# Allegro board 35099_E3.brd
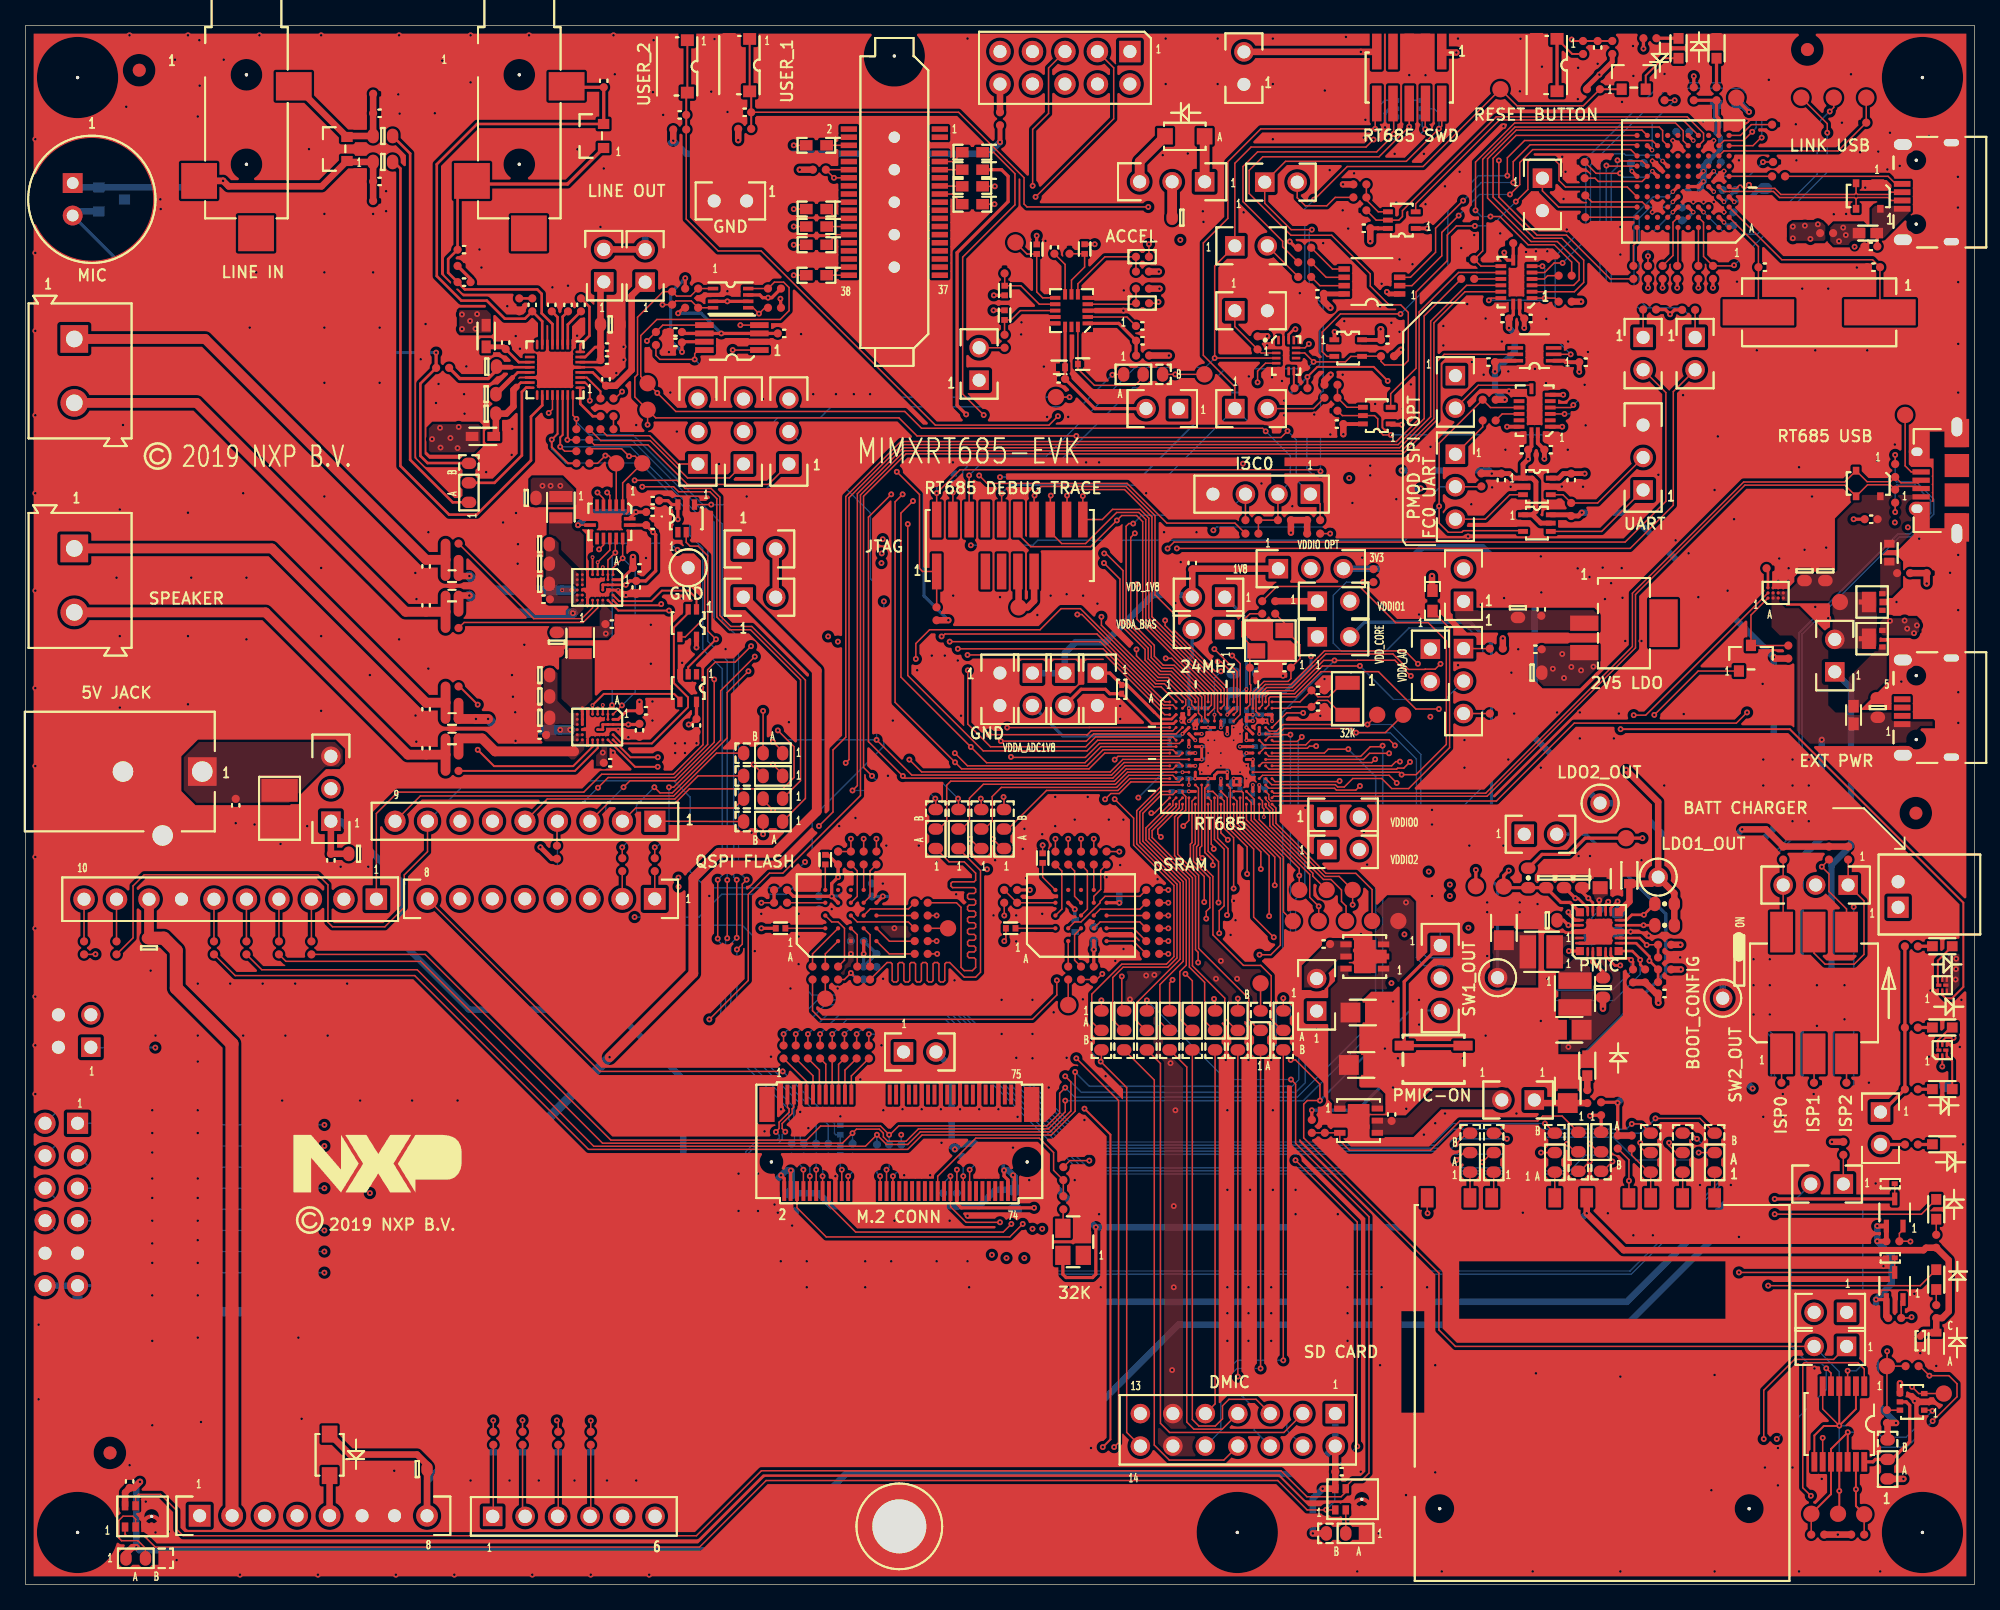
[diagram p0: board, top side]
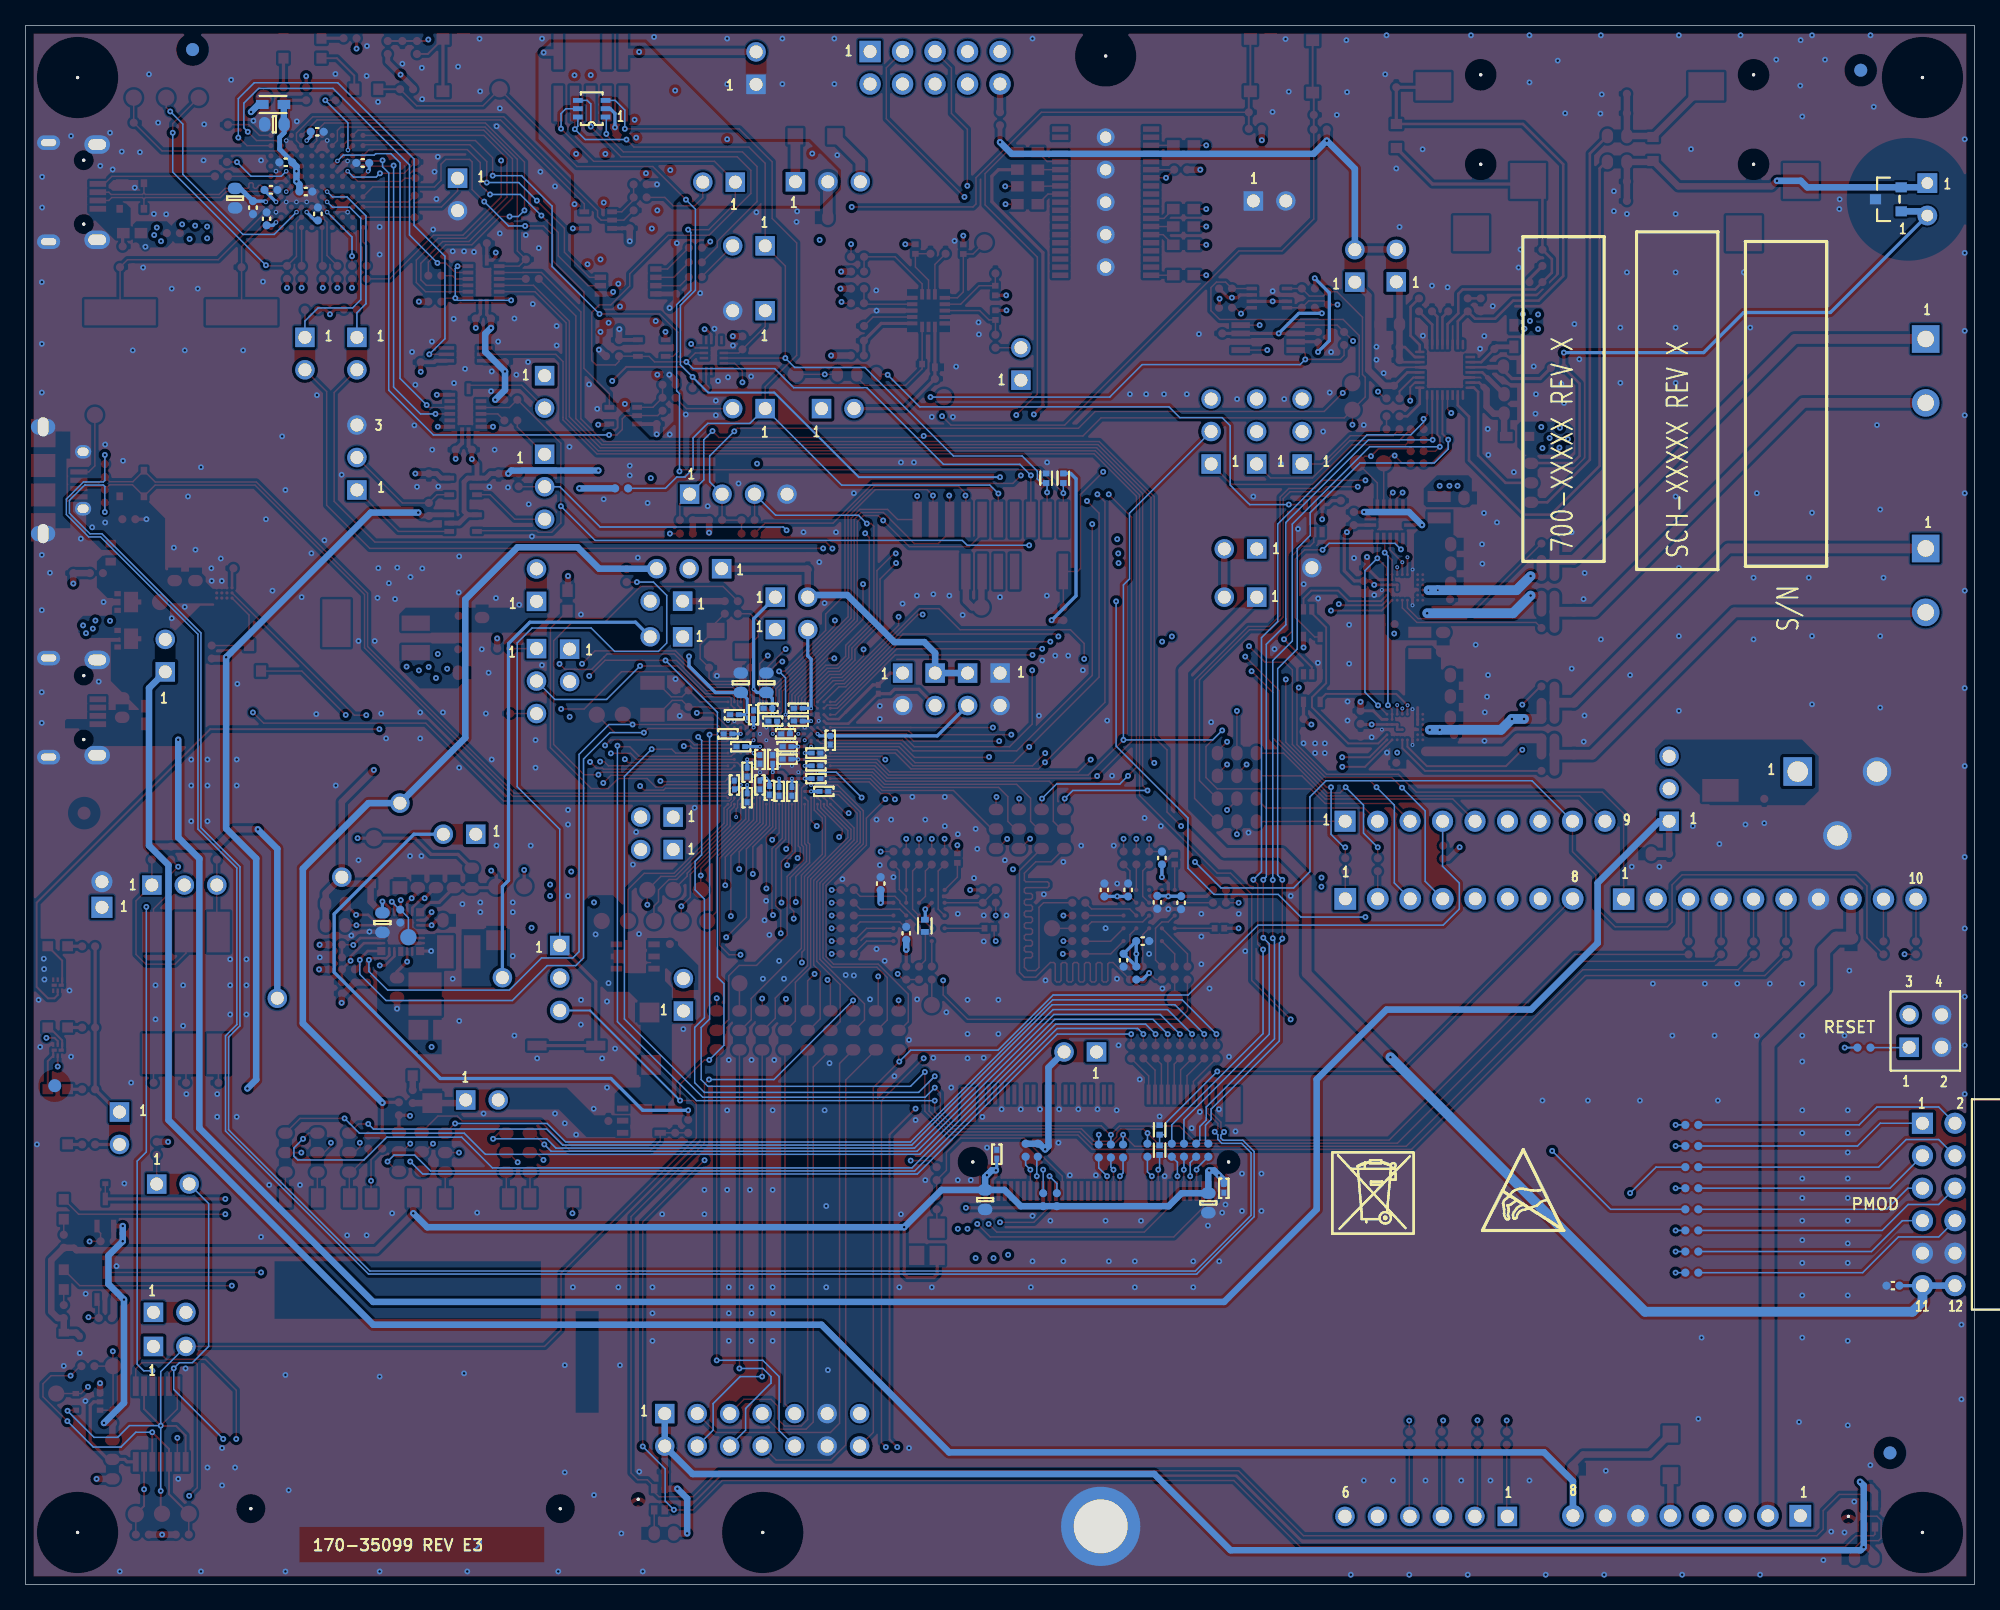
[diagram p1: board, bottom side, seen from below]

Outline 152.4 x 121.92 mm; copper layers: TOP, L2_GND, L3_IN1, L4_IN2, L5_PWR, BOTTOM. Coordinates in mm from the lower left corner of the outline.
Outline path: 0,121.92 152.4,121.92 152.4,0 0,0 0,121.92

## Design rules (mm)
constraint set DEFAULT: min track width 0.114
net group ACC_INT1: nets ACC_INT1 N18526318
net group BOOT0_LED: nets BOOT0_LED N17344064
net group BRIDGE_L_INTR-ISP: nets BRIDGE_L_INTR-ISP N17104052
net group CPCA: nets CPCA CPCB
net group FC5_RTS: nets FC5_RTS P1_7
net group HP_OUTL: nets HP_OUTL N169660511
net group HP_OUTR: nets HP_OUTR N169660621
net group IF_DETECT: nets IF_DETECT N17208284
net group IF_JTAG_TDI: nets IF_JTAG_TDI N17337803
net group IF_TCK_SWCLK: nets IF_TCK_SWCLK N19799835
net group LININL: nets LININL LININL_JACK
net group M2_USB_DN: nets M2_USB_DN USB0_DM_TRGT
net group M2_USB_DP: nets M2_USB_DP USB0_DP_TRGT
net group MCLK_CODEC: nets MCLK_CODEC P1_10_MCLK
net group N17337788: nets N17337786 N17337788
net group N19546738: nets N19546738 N19546843
net group N19830205: nets N19830205 N19830207
net group NRESET_POR: nets N16975069 NRESET_POR
net group OUTN_1: nets OUTN_1 VSN_1
net group OUTN_2: nets OUTN_2 VSN_2
net group OUTP_1: nets OUTP_1 VSP_1
net group OUTP_2: nets OUTP_2 VSP_2
net group P0_2_FC0_RX_LINK: nets N17103807 P0_2_FC0_RX_LINK
net group P0_3: nets N16974944 P0_3
net group P0_5_ADC0_0: nets N17760234 P0_5_ADC0_0
net group P0_6_ADC0_8: nets N17760260 P0_6_ADC0_8
net group P0_15_FC2_SCL: nets N16974981 P0_15_FC2_SCL
net group P0_16_FC2_SDA: nets N16975002 P0_16_FC2_SDA
net group P0_19_ADC0_2: nets N17760297 P0_19_ADC0_2
net group P0_20_ADC0_10: nets N17760315 P0_20_ADC0_10
net group P0_21: nets N19798378 P0_21
net group P0_22: nets N19798386 P0_22
net group P0_23_I2S_DATA_TX: nets N19798394 P0_23_I2S_DATA_TX
net group P0_24: nets N19798402 P0_24
net group P0_25: nets N19798410 P0_25
net group P0_29_FC4_TXD: nets N17760343 P0_29_FC4_TXD
net group P0_30_FC4_RXD: nets N17760363 P0_30_FC4_RXD
net group P1_3_SPI_CLK: nets N17760012 P1_3_SPI_CLK
net group P1_8: nets N19897088 P1_8
net group P1_20_OSPI_D0: nets P1_20_OSPI_D0 SIO0_AP
net group P1_22_OSPI_D2: nets P1_22_OSPI_D2 SIO2_AP
net group P2_26_SWDIO: nets N19799857 P2_26_SWDIO
net group QSPI_B_DQS: nets DQS_MX QSPI_B_DQS
net group SCLK_MX: nets P1_29_OSPI_B_SCK SCLK_MX
net group USB_DEBUGGER: nets USB_DM_LINK USB_DP_LINK
net group USB_ID: nets USB_ID USB_ID_LINK
net group VBAT: nets VBAT VBAT_BKUP
net group VREF_H: nets VREF_H VREF_L
net group XTALIN: nets XTALIN XTALOUT
net group ALT_INT_CODEC: nets ALT_INT_CODEC N17792155 P0_0_CODEC_ALT_IN
net group BRIDGE_INTR-ISP: nets BRIDGE_INTR-ISP N16974910 N17104054
net group BT_REG_ON_3V3: nets BT_REG_ON_3V3 N19527680 N19897050 N19897150 USDHC_SPWR WL_REG_ON_3V3
net group CARD_WR_PRT: nets CARD_WR_PRT LDO2_OUT M2_SD_CDM M2_SD_WK_B N19896842 N19896964 ON_B_SW P1_31_SD0_CMD P2_4_SD0_WR_PRT P2_9_SD0_CD SD_CMD
net group CS_AP: nets CS_AP CS_MX N16974934 N19546881 N19830189 N19830220 N19830414 NRESET_OSPI NRESET_OSPI_AP P1_13_SPI_MOSI P1_13_SPI_MOSI_A P1_19_OSPI_SSEL0 P2_19_PDM_CLK67 P2_19_PDM_CLK67_A QSPI_B_CS0 QSPI_B_DATA2 RST_AP RST_MX SIO2_MX VDD_MEM
net group DQS_AP: nets DQS_AP
net group FC1_CTS_SDA_SSEL0: nets FC1_CTS_SDA_SSEL0 P0_10 PIO0_10-FC1_CTS_SDA_SSELN0
net group FC1_SCK: nets FC1_SCK I2S_BCLK_CODEC N19897259 P0_7_I2S_CLK PIO0_7-FC1_SCK
net group FC1_TXD_SCL_MISO: nets FC1_TXD_SCL_MISO I2S_WS_CODEC N19897289 P0_8_I2S_WS PIO0_8-FC1_TXD_SCL_MISO
net group FC2_SCK: nets FC2_SCK P0_14 PIO0_14-FC2_SCK
net group FC4_CTS_SDA_SSEL0: nets FC4_CTS_SDA_SSEL0 P0_31 PIO0_31-FC4_CTS_SDA_SSELN0
net group FC5_CTS: nets FC5_CTS N17760099 P1_6_SPI_SS0
net group FC5_RXD: nets FC5_RXD N17760075 P1_5_SPI_MOSI
net group FC5_TXD: nets FC5_TXD N17760042 P1_4_SPI_MISO
net group I2S_DAO_CODEC: nets I2S_DAO_CODEC N19897327 P0_23_CODEC_DAO
net group IF_RST: nets IF_RST INT_B LDO1_OUT MODESEL0 MODESEL1 N17202709 N18503998 N19506203 N19526530 N19799787 NRESET_PB NRESET_TRGT SYSRST_B
net group LININR: nets ELECTRET_MIC LININR LININR_JACK MICBIAS N17851401
net group M2_SD_CLK: nets M2_SD_CLK N19896770 P1_30_SD0_CLK SD_CLK
net group M2_SD_DAT0: nets M2_SD_DAT0 N19896868 P2_0_SD0_D0 SD_DAT0
net group M2_SD_DAT1: nets M2_SD_DAT1 N19896897 P2_1_SD0_D1 SD_DAT1
net group M2_SD_DAT2: nets M2_SD_DAT2 N19896926 P2_2_SD0_D2 SD_DAT2
net group M2_SD_DAT3: nets M2_SD_DAT3 N19896944 P2_3_SD0_D3 SD_DAT3
net group MEM_1V8: nets MEM_1V8 N19546803 N19546823
net group NAND: nets P2_5_SD0_D4 P2_6_SD0_D5 P2_7_SD0_D6 P2_8_SD0_D7
net group P0_9_CODEC_DAI: nets I2S_DAI_CODEC N19897307 P0_9_CODEC_DAI
net group P0_17_FC2_SDA: nets N17759973 N18526137 P0_17_FC2_SDA
net group P0_18_FC2_SCL: nets N17759955 N18526135 P0_18_FC2_SCL
net group P1_21_OSPI_D1: nets SIO1_AP
net group P1_23_OSPI_D3: nets SIO3_AP
net group P1_24_OSPI_D4: nets SIO4_AP
net group P1_25_OSPI_D5: nets SIO5_AP
net group P1_26_OSPI_D6: nets SIO6_AP
net group P1_27_OSPI_D7: nets SIO7_AP
net group P2_17_PDM_CLK23_A: nets P2_17_PDM_CLK23 P2_17_PDM_CLK23_A QSPI_B_DATA4 SIO4_MX
net group P2_18_PDM_CLK45_A: nets P2_18_PDM_CLK45 P2_18_PDM_CLK45_A QSPI_B_DATA5 SIO5_MX
net group P2_21_PDM_DATA23_A: nets N20219970 P2_21_PDM_DATA23 P2_21_PDM_DATA23_A
net group P2_22_PDM_DATA45_A: nets P2_22_PDM_DATA45 P2_22_PDM_DATA45_A QSPI_B_DATA6 SIO6_MX
net group P2_23_PDM_DATA67_A: nets P2_23_PDM_DATA67 P2_23_PDM_DATA67_A QSPI_B_DATA7 SIO7_MX
net group PDM_CLK01_ONBOARD: nets P2_16_PDM_CLK01 PDM_CLK01_EXT PDM_CLK01_ONBOARD
net group PDM_DATA01_EXT: nets P2_20_PDM_DATA01 PDM_DATA01_EXT PDM_DATA01_ONBOARD
net group QSPI_B_DATA0: nets N16975000 P1_11_SPI_CLK P1_11_SPI_CLK_A QSPI_B_DATA0 SIO0_MX
net group QSPI_B_DATA1: nets N16974979 P1_12_SPI_MISO P1_12_SPI_MISO_A QSPI_B_DATA1 SIO1_MX
net group QSPI_B_DATA3: nets N16974908 P1_14_SPI_SS0 P1_14_SPI_SS0_A QSPI_B_DATA3 SIO3_MX
net group SCLK_AP: nets SCLK_AP
net group SD_RST_N: nets M2_SD_RST_B N19508206 N19531396 N19896972 P2_10_SD0_RST_N SD_RST_N VDD_TARGET
net group SEL_ON_DMIC_1: nets AVDD P1V8_CODEC SEL_ON_DMIC_1 SEL_ON_DMIC_2
net group USB1_VDD3V3: nets FC0_RXD N19519289 USB1_VDD3V3 VDD_LDO_3V3
net group V_LED: nets N17023483 N17023485 N17023487 V_LED
net group VBUS0_TARGET: nets VBUS0_TARGET
net group VDD_CODEC: nets M2_32K_3V3 MICVDD N17792148 N19898667 P2_29_I3C0_SCL P2_30_I3C0_SDA P2_31_I3C0_PUR SCL_CODEC SDA_CODEC
net group VDD_LINK: nets IF_TDO_SWO N17337994 N17338012 N17338109 N17338127 N19799813 VDD_LINK

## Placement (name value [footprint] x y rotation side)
BH1  SMTSO-M25  [MH244-166T]  68.33 4.54 0 top
C1  0.1uF  [CC0402_25]  122.94 120.21 270 top
C2  220PF  [CC0402_25]  45.21 117.6 90 top
C3  0.1uF  [CC0402_25]  56.24 115.14 180 top
C4  220PF  [CC0402_25]  27.69 115.06 0 top
C5  0.1uF  [CC0402_25]  51.16 114.94 180 top
C6  4.7uF  [CC0603_OV]  27.94 113.28 180 top
C7  4.7uF  [CC0603_OV]  27.94 111.25 180 top
C8  220PF  [CC0402_25]  27.69 109.73 0 top
C9  1uF  [CC0402_25]  144.3 104.65 180 top
C10  0.1uF  [CC0402_25]  104.65 106.07 0 top
C11  220PF  [CC0402_25]  34.29 104.39 0 top
C12  10uF  [CC0603_OV]  90.42 106.9 0 top
C13  27PF  [CC0402_25]  136.02 103.02 0 top
C14  27PF  [CC0402_25]  144.51 103.02 0 top
C15  0.1uF  [CC0402_25]  34.29 101.85 0 top
C16  0.1uF  [CC0402_25]  101.02 100.94 0 top
C17  0.1uF  [CC0402_25]  39.62 100.08 90 top
C18  2.2UF  [CC0402_25]  41.15 100.08 90 top
C19  2.2UF  [CC0402_25]  42.42 100.08 90 top
C20  2.2UF  [CC0402_25]  43.43 100.08 270 top
C21  4.7uF  [CC0603_OV]  45.72 98.55 0.3 top
C22  0.1uF  [CC0402_25]  115.49 99.01 0 top
C23  0.1uF  [CC0402_25]  117.7 99.01 0 top
C24  0.1uF  [CC0402_25]  87.35 97.27 0 top
C25  0.1uF  [CC0402_25]  106.5 97.33 180 top
C26  0.1uF  [CC0402_25]  37.54 97.13 90 top
C27  1uF  [CC0402_25]  45.47 96.77 0 top
C28  0.1uF  [CC0402_25]  80.78 94.29 180 top
C29  4.7UF  [CC0402_TOL0P2]  80.82 95.19 180 top
C30  0.1uF  [CC0402_25]  45.47 95.76 0 top
C31  0.1uF  [CC0402_25]  87.34 98.42 0 top
C32  4.7uF  [CC0603_OV]  36.07 95.25 180 top
C33  0.1uF  [CC0402_25]  45.39 94.26 90 top
C34  4.7uF  [CC0603_OV]  36.02 93.09 180 top
C35  4.7uF  [CC0603_OV]  36.02 91.57 180 top
C36  0.1uF  [CC0402_25]  102.54 90.75 0 top
C37  0.1uF  [CC0402_25]  116.99 88.75 0 top
C38  0.1uF  [CC0402_25]  119.28 88.75 0 top
C39  0.22UF  [CC0402_25]  120.87 86.37 270 top
C40  0.22UF  [CC0402_25]  115.4 86.37 270 top
C41  22uF  [CC0603_OV]  39.15 84.98 180 top
C42  2.2UF  [CC0402_25]  144.32 83.31 180 top
C43  10uF  [CC0603_OV]  40.2 81.36 180 top
C44  10uF  [CC0603_OV]  40.2 79.83 180 top
C45  18pF  [CC0402_25]  31.32 79.63 270 top
C46  1uF  [CC0402_25]  48.01 79.5 0 top
C47  4.7uF  [CC0603_OV]  139.12 79.27 90 top
C48  4.7uF  [CC0603_OV]  140.74 79.27 90 top
C49  10uF  [CC0603_OV]  40.2 78.26 180 top
C50  4.7uF  [CC0603_OV]  116.7 76.38 90 top
C51  0.1uF  [CC0402_25]  118.53 76.26 90 top
C52  1uF  [CC0402_25]  47.75 77.98 270 top
C53  0.1uF  [CC0402_25]  40.5 77.05 180 top
C54  18pF  [CC0402_25]  31.32 76.58 90 top
C55  1uF  [CC0402_25]  45.85 75.11 0 top
C56  0.1uF  [CC0402_25]  118.06 73.14 180 top
C57  22uF  [CC0603_OV]  41.55 73.69 270 top
C58  6.0PF  [CC0402_25]  96.24 71.7 0 top
C59  6.0PF  [CC0402_25]  98.44 71.7 180 top
C60  4.7uF  [CC0603_OV]  117.81 71.31 180 top
C61  10uF  [CC0603_OV]  40.22 71.12 180 top
C62  18pF  [CC0402_25]  101.07 69.93 0 top
C63  0.1uF  [CC0402_25]  52.47 67.18 270 top
C64  10uF  [CC0603_OV]  40.22 69.45 180 top
C65  18pF  [CC0402_25]  31.32 68.45 270 top
C66  1uF  [CC0402_25]  48.51 68.33 0 top
C67  4.7uF  [CC0603_OV]  144.85 68.58 90 top
C68  0.1uF  [CC0201]  85.72 70.01 90 top
C69  18pF  [CC0402_25]  101.07 68.63 0 top
C70  10uF  [CC0603_OV]  40.22 67.78 180 top
C71  1uF  [CC0402_25]  48.01 66.8 270 top
C72  0.1uF  [CC0402_25]  40.2 66.43 180 top
C73  18pF  [CC0402_25]  31.32 65.41 90 top
C74  1uF  [CC0402_25]  45.72 64.26 0 top
C75  0.1uF  [CC0402_25]  16.43 60.93 270 top
C76  100UF  [CC1210]  19.86 60.71 270 top
C77  4.7uF  [CC0603_OV]  26.04 57.14 0 top
C78  0.1uF  [CC0402_25]  23.88 56.63 270 top
C79  1.0 UF  [CC0603_OV]  120.3 55.26 90 top
C80  1.0 UF  [CC0603_OV]  118.91 55.26 90 top
C81  4.7uF  [CC0603_OV]  119 51.94 180 top
C82  2.2uF  [CC0603_0402_NSP]  123.13 55.19 90 top
C83  2.2uF  [CC0603_OV]  121.73 55.26 90 top
C84  1.0 UF  [0603_CC]  125.42 55.46 90 top
C85  10uF  [CC0603_OV]  9.65 49.78 270 top
C86  10uF  [CC0603_0805_NSP]  115.61 51.35 90 top
C87  2.2uF  [CC0603_OV]  123.35 46.68 270 top
C88  10uF  [CC0603_0805_NSP]  120.72 43.38 180 top
C89  10uF  [CC0603_0805_NSP]  120.6 38.61 90 top
C90  10uF  [CC0603_OV]  30.63 9.02 180 top
C91  4.7uF  [CC0603_OV]  132.94 114.2 0 bottom
C92  0.1uF  [CC0402_25]  129.59 113.61 180 bottom
C93  0.1uF  [CC0402_25]  132.05 111.23 0 bottom
C94  0.1uF  [CC0402_25]  126.03 111.18 0 bottom
C95  0.1uF  [CC0402_25]  133.21 109.07 180 bottom
C96  0.1uF  [CC0402_25]  130.48 108.94 180 bottom
C97  10uF  [CC0603_OV]  136.02 108.42 270 bottom
C98  0.1uF  [CC0402_25]  134.62 107.68 270 bottom
C99  0.1uF  [CC0402_25]  129.54 107.19 90 bottom
C100  0.1uF  [CC0402_25]  133.55 106.81 90 bottom
C101  10uF  [CC0603_OV]  96.47 70.52 90 bottom
C102  0.1uF  [CC0201]  96.97 68.02 0 bottom
C103  0.1uF  [CC0201]  94.34 68.52 0 bottom
C104  0.1uF  [CC0201]  90.59 64.02 180 bottom
C105  0.1uF  [CC0201]  94.97 62.52 270 bottom
C106  0.1uF  [CC0201]  97.47 66.52 0 bottom
C107  0.1uF  [CC0201]  91.97 67.52 0 bottom
C108  0.1uF  [CC0201]  95.47 68.02 90 bottom
C109  0.1uF  [CC0201]  89.47 66.02 270 bottom
C110  0.1uF  [CC0201]  92.97 66.52 0 bottom
C111  0.1uF  [CC0201]  92.85 65.52 0 bottom
C112  0.1uF  [CC0201]  93.97 67.52 0 bottom
C113  0.1uF  [CC0201]  96.47 65.52 0 bottom
C114  0.1uF  [CC0201]  90.59 65.02 180 bottom
C115  0.01uF  [CC0201]  94.97 64.52 270 bottom
C116  0.1uF  [CC0201]  92.85 64.55 0 bottom
C117  0.1uF  [CC0201]  95.97 63.52 270 bottom
C118  10uF  [CC0603_OV]  94.47 70.52 90 bottom
C119  0.1uF  [CC0201]  93.47 62.02 270 bottom
C120  0.1uF  [CC0201]  92.47 62.02 270 bottom
C121  0.1uF  [CC0201]  93.97 64.52 90 bottom
C122  0.1uF  [CC0201]  90.59 63.02 180 bottom
C123  0.1uF  [CC0201]  96.97 62.52 90 bottom
C124  0.1uF  [CC0201]  94.23 62.1 270 bottom
C125  0.1uF  [CC0201]  89.97 62.02 180 bottom
C126  0.1uF  [CC0201]  95.97 61.52 270 bottom
C127  2.2UF  [CC0402_25]  63.54 56.81 90 bottom
C128  0.1uF  [CC0402_25]  65.04 50.32 180 bottom
C129  0.1uF  [CC0402_25]  62.04 53.32 270 bottom
C130  2.2UF  [CC0402_25]  66.18 54.32 90 bottom
C131  0.47UF  [CC0603_OV]  124.5 51.76 270 bottom
C132  0.1uF  [CC0402_25]  63.9 53.35 270 bottom
C133  2.2UF  [CC0402_25]  68.04 54.32 90 bottom
C134  0.1uF  [CC0402_25]  6.37 23.37 180 bottom
C135  10uF  [CC0603_0805_NSP]  104.44 40.63 0 top
C136  0.1uF  [CC0402_25]  106.82 36.76 90 top
C137  10uF  [CC0603_0805_NSP]  104.57 44.73 0 top
C138  0.1uF  [CC0402_25]  101.51 50.09 180 top
C139  0.1uF  [CC0402_25]  114.4 95.61 0 top
C140  0.1uF  [CC0402_25]  122.01 95.59 0 top
C143  0.1uF  [CC0402_25]  80.45 104.58 90 top
C217  1uF  [CC0402_25]  85.53 54.82 90 bottom
C218  0.1uF  [CC0402_25]  83.53 50.93 90 bottom
C219  4.7UF  [CC0402_TOL0P2]  82.08 51.51 270 bottom
C250  10uF  [CC0603_OV]  77.37 30.09 270 bottom
C251  0.1uF  [CC0201]  76.45 33.65 90 bottom
C252  10uF  [CC0603_OV]  59.91 29.84 270 bottom
C253  0.1uF  [CC0201]  58.7 30.98 270 bottom
C316  1uF  [CC0402_25]  91.23 79.89 90 top
C317  1uF  [CC0402_25]  66.54 48.82 270 bottom
C319  0.1uF  [CC0201]  145.82 25.54 180 top
C320  0.1uF  [CC0201]  145.82 31.34 180 top
C321  0.01uF  [CC0201]  148.16 19.06 270 top
C322  0.1uF  [CC0402_25]  49.04 84.76 180 top
C328  0.1uF  [CC0402_25]  49.04 82.85 0 top
C329  0.1uF  [CC0402_25]  50.82 97.95 180 top
C330  0.1uF  [CC0402_25]  50.82 97.14 180 top
C331  0.1uF  [CC0402_25]  49.04 83.87 0 top
C332  0.1uF  [CC0402_25]  128.17 46.22 0 top
C333  0.1uF  [CC0402_25]  59.33 97.84 0 top
C336  0.1uF  [CC0402_25]  8.14 8.06 90 top
C337  0.1uF  [CC0402_25]  102.93 8.82 0 top
C338  0.1uF  [CC0201]  91.97 68.52 0 bottom
D1  150060RS75000  [LED_0603]  129.26 120.14 270 top
D2  150060RS75000  [LED_0603]  132.23 120.14 90 top
D3  PESD5V0S2BT  [SOT23_A]  44.2 113.28 90 top
D4  PESD5V0S2BT  [SOT23_A]  24.13 112.27 90 top
D5  PMEG1020EH  [SOD123LF]  90.65 113.26 0 top
D6  PMEG4010CPA  [SOT1061]  144.4 76.83 270 top
D7  PMEG4010CPA  [SOT1061]  144.4 73.96 270 top
D8  BLUE LED  [LED_0603]  149.89 49.91 0 top
D9  150060RS75000  [LED_0603]  149.89 43.56 0 top
D10  LED_GREEN  [LED_0603]  149.89 38.74 0 top
D11  150060RS75000  [LED_0603]  149.89 34.42 0 top
D12  MBR120VLSFT1G  [SOD-123]  23.77 10.13 270 top
D13  PESD3V3L5UY  [SOT-363_0P65_SMT]  108.13 115.42 0 bottom
D14  PESD5V0S2BT  [SOT23_A]  6.73 108.33 90 bottom
D15  150060RS75000  [LED_0603]  122.13 40.57 90 top
D22  150060RS75000  [LED_0603]  149.41 23.84 90 top
D23  150060RS75000  [LED_0603]  149.41 29.34 90 top
D26  PESD3V3S1UB  [SOD523]  149.41 18.84 270 top
FB1  330 OHM  [IND_1608]  145.75 80.7 90 top
J1  HDR 2X5  [HDR205]  86.36 119.89 270 top
J2  FTSH-105-01-L-DV-K  [HDR205_10M_50_SM_K]  108.2 117.86 180 top
J3  SJ-3524-SMT  [CON4_JACK_5X17]  17.27 115.57 0 top
J4  SJ-3524-SMT  [CON4_JACK_5X17]  38.61 115.57 0 top
J5  USB MICRO B  [USB_MICRO_B_0P65_SM_RA]  149.7 108.89 90 top
J6  USB MICRO B  [USB_MICRO_B_0P65_SM_RA]  149.7 68.58 90 top
J7  USB AB 5  [CON9_MICROAB_USB_SHELL_TH]  151.03 86.36 90 top
J11  TB_1X2  [CON2_TB_5MM_10X7P5MM_TH]  3.81 97.41 270 top
J16  HDR TH 1X3  [HDR103]  126.49 85.6 180 top
J18  HDR_1X4  [JUMP1X4-6040]  100.47 85.27 180 top
J19  HDR 2X10  [HDR210_FTSH_SM]  76.96 81.25 90 top
J20  TB_1X2  [CON2_TB_5MM_10X7P5MM_TH]  3.81 81.03 270 top
J21  S2B-PH-KL  [HDR1X2_2P0_5P9X7P6]  146.43 52.96 90 top
J24  DC10LP  [CON3_SKT_DC_POWER]  13.82 63.58 180 top
J25  HDR 1X2  [HDR102]  56.39 108.2 270 top
J26  HDR 1X2  [HDR102]  76.19 71.28 0 top
J27  CON_1X8  [CON_1X8_SKT_2P54_TH]  49.2 53.62 270 top
J28  CON_1X10  [HDR110]  27.43 53.59 270 top
J29  CON_1X8  [CON_1X8_SKT_2P54_TH]  13.61 5.37 90 top
J30  CON_1X6  [CON_SKT1X6_TH]  36.53 5.32 90 top
J31  TSW-107-07-F-D  [JUMP2X7-6040]  102.42 13.36 270 top
J32  CONN_SD_CARD 9  [CON_SDCARD_28P9X29_SM_RA]  123.26 14.98 0 top
J35  SKT_2X2  [SKT2X2_TH_SSQ]  5.11 42.01 0 bottom
J36  PPPC062LJBN-RC  [SKT2X6_100_TH_RA]  4.06 36.07 180 bottom
J38  CON 2X19 M  [CON_MIC_38M_25_SM]  67.94 108.11 90 top
J45  M.2 MINI CARD  [CON_67_0P5_22X7P75_RA]  68.33 34.42 0 top
J47  SKT_1X9  [CON_SKT1X9_TH]  49.21 59.69 270 top
JP1  HDR 1X2  [HDR102]  118.62 109.98 0 top
JP2  HDR TH 1X3  [HDR103]  92.2 109.7 270 top
JP3  HDR 1X2  [HDR102]  94.56 99.61 90 top
JP4  HDR 1X2  [HDR102]  111.81 94.54 0 top
JP6  HDR TH 1X3  [HDR103]  52.58 87.63 180 top
JP7  HDR TH 1X3  [HDR103]  56.13 87.63 180 top
JP8  HDR TH 1X3  [HDR103]  59.69 87.63 180 top
JP9  HDR 1X2  [HDR102]  83.81 71.28 0 top
JP10  HDR 1X2  [HDR102]  81.27 71.28 0 top
JP11  HDR TH 1X3  [HDR103]  23.88 59.69 180 top
JP12  HDR TH 1X3  [HDR103]  97.97 79.44 90 top
JP13  HDR TH 1X3  [HDR103]  142.52 54.7 270 top
JP14  HDR 1X2  [HDR102]  142.4 18.61 270 top
JP15  HDR 1X2  [HDR102]  90.16 91.96 270 top
JP16  HDR TH 1X3  [HDR103]  110.63 49.97 0 top
JP17  HDR 1X2  [HDR102]  94.56 91.96 90 top
JP18  HDR 1X2  [HDR102]  94.56 104.69 90 top
JP19  HDR 1X2  [HDR102]  96.9 109.68 90 top
JP20  HDR 1X2  [HDR102]  101.76 60.01 90 top
JP21  HDR TH 1X3  [HDR103]  111.81 88.39 0 top
JP22  HDR TH 1X3  [HDR103]  112.45 73.19 0 top
JP23  HDR 1X2  [HDR102]  101.02 76.9 90 top
JP24  HDR 1X2  [HDR102]  93.77 74.68 270 top
JP25  HDR 1X2  [HDR102]  78.73 71.28 0 top
JP26  HDR 1X2  [HDR102]  109.86 73.15 0 top
JP27  HDR 1X2  [HDR102]  101.76 57.47 90 top
JP28  HDR 1X2  [HDR102]  93.77 77.22 270 top
JP29  HDR 1X2  [HDR102]  101.02 74.11 90 top
JP30  HDR 1X2  [HDR102]  74.57 94.18 180 top
JS1  HDR 1X2 TH  [SH_HDR102_BOTTOM]  95.28 117.32 180 top
JS2  HDR 1X2 TH  [SH_HDR102_BOTTOM]  45.21 101.87 180 top
JS3  HDR 1X2 TH  [SH_HDR102_BOTTOM]  48.45 101.85 180 top
JS5  HDR 1X2 TH  [SH_HDR102_BOTTOM]  126.49 97.54 0 top
JS6  HDR 1X2 TH  [SH_HDR102_BOTTOM]  130.56 97.54 0 top
JS7  HDR 1X2 TH  [SH_HDR102_BOTTOM]  56.12 80.99 90 top
JS8  HDR 1X2 TH  [SH_HDR102_BOTTOM]  112.45 76.89 180 top
JS9  HDR 1X2 TH  [SH_HDR102_BOTTOM]  56.12 77.22 90 top
JS10  HDR 1X2 TH  [SH_HDR102_BOTTOM]  141.48 71.37 180 top
JS11  HDR 1X2 TH  [SH_HDR102_BOTTOM]  117.2 58.67 90 top
JS12  HDR 1X2 TH  [SH_HDR102_BOTTOM]  68.65 41.64 90 top
JS13  HDR 1X2 TH  [SH_HDR102_BOTTOM]  145.06 36.95 0 top
JS14  HDR 1X2 TH  [SH_HDR102_BOTTOM]  117.98 37.89 270 top
JS15  HDR 1X2 TH  [SH_HDR102_BOTTOM]  142.4 21.28 270 top
JS16  HDR 1X2 TH  [SH_HDR102_BOTTOM]  100.96 44.84 180 top
JS17  HDR 1X2 TH  [SH_HDR102_BOTTOM]  142.15 31.32 270 top
L1  220Ohm  [IND_0603]  144.07 105.69 180 top
L2  600OHM  [IND_1P8X1MM_SM]  36.02 97.64 270 top
L3  600OHM  [IND_1P8X1MM_SM]  35.76 89.79 0 top
L4  1uH  [IND_2016A]  41.86 84.25 270 top
L5  120OHM  [IND_0402]  33.35 78.87 180 top
L6  120OHM  [IND_0402]  33.35 77.34 180 top
L7  1uH  [IND_2016A]  43.37 73.63 270 top
L8  220Ohm  [IND_0603]  142.95 68 90 top
L9  120OHM  [IND_0402]  33.35 67.69 180 top
L10  120OHM  [IND_0402]  33.35 66.17 180 top
L11  2.2uH  [IND_2016_2520_NSP]  118.53 49.48 180 top
L12  2.2uH  [IND_2016_2520_NSP]  121.16 46.17 270 top
L13  600OHM  [IND_1P8X1MM_SM]  133.05 115.75 0 bottom
NOREF  -  []  124.61 51.55 90 top
NOREF#2  -  []  122.08 30.24 0 top
NOREF#3  -  []  7.34 6.69 0 top
NOREF#4  -  []  115.37 100.6 90 top
NOREF#5  -  []  145.2 76.18 90 top
NOREF#6  -  []  1.52 23.37 0 top
NOREF#7  -  []  0.41 89.81 0 top
NOREF#8  -  []  115.37 103.1 0 top
NOREF#9  -  []  20.95 30.66 0 top
NOREF#10  -  []  80.52 100.63 0 top
NOREF#11  -  []  137.32 51.02 0 top
NOREF#12  -  []  115.61 50.38 90 top
NOREF#13  -  []  0.02 20.12 0 top
NOREF#14  -  []  137.95 106.14 0 top
NOREF#15  -  []  116.34 103.57 0 top
NOREF#16  -  []  1.3 35.28 0 top
NOREF#17  -  []  147.85 66.08 90 top
NOREF#18  -  []  58.33 33.04 90 top
NOREF#19  -  []  27.24 58.42 0 top
NOREF#20  -  []  123.56 52.6 0 top
NOREF#21  -  []  104.49 6.66 90 top
NOREF#22  -  []  0.92 84.23 0 top
NOREF#23  -  []  80.52 100.13 90 top
NOREF#24  -  []  55.02 116.77 0 top
NOREF#25  -  []  82.62 95.54 90 top
NOREF#26  -  []  147.85 106.39 90 top
NOREF#27  -  []  117.89 103.65 90 top
NOREF#28  -  []  143.35 79.99 0 top
NOREF#29  -  []  164.78 61.75 90 top
NOREF#30  -  []  3.81 92.41 90 top
NOREF#31  -  []  88.97 51.52 90 top
NOREF#32  -  []  125.38 30.24 0 top
NOREF#33  -  []  117.56 116.73 90 top
NOREF#34  -  []  152.4 0 90 top
NOREF#35  -  []  145.08 51.01 90 top
NOREF#36  -  []  118.71 52.9 0 top
NOREF#37  -  []  30.1 -57.8 0 top
NOREF#38  -  []  109.6 30.24 0 top
NOREF#39  -  []  57.33 30.39 0 top
NOREF#40  -  []  42.93 68.31 0 top
NOREF#41  -  []  120.26 47.27 0 top
NOREF#42  -  []  147.85 66.08 90 top
NOREF#43  -  []  28.89 59.69 0 top
NOREF#44  -  [unnamed#2]  6.6 10.29 0 top
NOREF#45  -  [unnamed#2]  94.75 4.06 0 top
NOREF#46  -  []  144.69 42.58 90 top
NOREF#47  -  []  4.06 33.53 90 top
NOREF#48  -  [unnamed#2]  148.34 117.86 0 top
NOREF#49  -  []  42.93 76.72 90 top
NOREF#50  -  []  54.42 116.72 0 top
NOREF#51  -  []  45.44 68.31 90 top
NOREF#52  -  []  0 121.92 0 top
NOREF#53  -  []  132.2 115.75 0 top
NOREF#54  -  []  0.41 89.81 90 top
NOREF#55  -  []  76.48 85.65 0 top
NOREF#56  -  []  80.29 98.13 90 top
NOREF#57  -  []  117.76 93.51 0 top
NOREF#58  -  []  150.6 64.71 90 top
NOREF#59  -  []  164.78 61.75 90 top
NOREF#60  -  []  119.31 91 90 top
NOREF#61  -  [unnamed#2]  148.34 4.06 0 top
NOREF#62  -  []  112.95 30.24 0 top
NOREF#63  -  []  58.33 33.04 0 top
NOREF#64  -  []  103.59 41.08 0 top
NOREF#65  -  []  147.55 72.91 90 top
NOREF#66  -  []  0 0 0 top
NOREF#67  -  []  34.92 89.79 0 top
NOREF#68  -  []  34.86 88.49 90 top
NOREF#69  -  []  143.35 77.89 90 top
NOREF#70  -  []  7.78 6.15 0 top
NOREF#71  -  []  120.15 37.76 0 top
NOREF#72  -  []  121.85 36.86 90 top
NOREF#73  -  []  0.02 21.67 0 top
NOREF#74  -  []  54.42 116.72 90 top
NOREF#75  -  []  103.61 44.73 0 top
NOREF#76  -  []  113.45 50.5 90 top
NOREF#77  -  []  123.58 54.34 0 top
NOREF#78  -  []  88.97 51.52 0 top
NOREF#79  -  []  42.93 76.72 0 top
NOREF#80  -  []  55.02 116.77 90 top
NOREF#81  -  []  8.72 5.58 90 top
NOREF#82  -  []  80.31 98.13 0 top
NOREF#83  -  []  89.47 61.02 0 top
NOREF#84  -  []  45.54 76.98 0 top
NOREF#85  -  []  43.14 66.06 90 top
NOREF#86  -  []  10.94 3.94 90 top
NOREF#87  -  []  24.89 53.59 0 top
NOREF#88  -  []  119.63 48.58 90 top
NOREF#89  -  []  0 0 0 top
NOREF#90  -  []  147.85 106.39 90 top
NOREF#91  -  []  164.78 102.06 90 top
NOREF#92  -  []  102.42 7.49 0 top
NOREF#93  -  [unnamed#2]  139.34 120.04 0 top
NOREF#94  -  []  118.16 116.78 0 top
NOREF#95  -  []  145.45 72.91 0 top
NOREF#96  -  []  103.24 5.83 90 top
NOREF#97  -  []  57.33 30.39 90 top
NOREF#98  -  []  137.95 65.83 0 top
NOREF#99  -  []  117.48 49.48 0 top
NOREF#100  -  []  39.43 93.6 90 top
NOREF#101  -  []  150.24 46.43 90 top
NOREF#102  -  []  123.73 30.24 0 top
NOREF#103  -  []  101.98 8.03 0 top
NOREF#104  -  []  97.47 61.02 90 top
NOREF#105  -  []  117.08 30.24 0 top
NOREF#106  -  []  0.92 100.61 0 top
NOREF#107  -  []  164.78 61.75 90 top
NOREF#108  -  []  81.79 100.9 0 top
NOREF#109  -  []  0.41 73.43 0 top
NOREF#110  -  []  109.08 8.03 0 top
NOREF#111  -  []  144.15 77.09 90 top
NOREF#112  -  [unnamed#2]  4.06 117.86 0 top
NOREF#113  -  []  57.98 37.54 0 top
NOREF#114  -  []  118.71 49.8 90 top
NOREF#115  -  []  59.33 30.77 0 top
NOREF#116  -  []  150.46 46.34 90 top
NOREF#117  -  []  22.23 28.47 0 top
NOREF#118  -  []  149.31 47.39 0 top
NOREF#119  -  []  116.79 90.55 90 top
NOREF#120  -  []  120.26 45.07 90 top
NOREF#121  -  []  144.65 74.22 90 top
NOREF#122  -  []  43.59 -7.82 0 top
NOREF#123  -  []  122.68 -5.75 90 top
NOREF#124  -  []  164.78 102.06 90 top
NOREF#125  -  []  116.79 93.05 0 top
NOREF#126  -  []  113.45 50.5 0 top
NOREF#127  -  []  146.43 52.96 90 top
NOREF#128  -  []  33.86 90.29 0 top
NOREF#129  -  []  49.55 120.83 0 top
NOREF#130  -  []  81.29 98.35 90 top
NOREF#131  -  []  119.31 91 0 top
NOREF#132  -  []  59.33 30.77 90 top
NOREF#133  -  []  44.2 16.33 0 top
NOREF#134  -  []  50.15 116.68 90 top
NOREF#135  -  []  8.11 89.81 90 top
NOREF#136  -  []  114.29 106.25 0 top
NOREF#137  -  []  81.42 95.54 0 top
NOREF#138  -  []  122.68 -4.65 90 top
NOREF#139  -  []  83.07 100.63 90 top
NOREF#140  -  []  97.47 61.02 90 top
NOREF#141  -  []  119.58 30.24 0 top
NOREF#142  -  []  124.61 50.15 90 top
NOREF#143  -  []  122.68 -10.85 90 top
NOREF#144  -  []  59.33 30.77 0 top
NOREF#145  -  []  93.88 -13.92 90 top
NOREF#146  -  []  9.85 5.32 90 top
NOREF#147  -  []  145.08 56.91 0 top
NOREF#148  -  []  143.14 109.59 0 top
NOREF#149  -  []  137.08 9.23 90 top
NOREF#150  -  []  143.14 85.11 0 top
NOREF#151  -  []  110.58 5.93 0 top
NOREF#152  -  []  142.4 41.5 90 top
NOREF#153  -  []  5.11 42.01 90 top
NOREF#154  -  [unnamed#2]  8.89 118.43 0 top
NOREF#155  -  []  127.46 8.64 0 top
NOREF#156  -  []  121.57 42.93 90 top
NOREF#157  -  []  114.65 30.24 0 top
NOREF#158  -  []  149.89 42.22 0 top
NOREF#159  -  []  -383.9 -332.05 0 top
NOREF#160  -  []  132.15 115.25 90 top
NOREF#161  -  []  150.6 105.01 90 top
NOREF#162  -  []  122.16 52.6 0 top
NOREF#163  -  []  125.28 54.34 90 top
NOREF#164  -  []  34.72 98.54 0 top
NOREF#165  -  []  145.2 73.31 90 top
NOREF#166  -  []  103.48 40.63 0 top
NOREF#167  -  []  150.46 41.26 0 top
NOREF#168  -  []  164.78 61.75 90 top
NOREF#169  -  []  -62.59 101.52 0 top
NOREF#170  -  []  117.56 116.73 0 top
NOREF#171  -  []  45.54 66.06 0 top
NOREF#172  -  []  131.15 115.25 0 top
NOREF#173  -  []  129.58 30.24 0 top
NOREF#174  -  []  53.75 120.83 90 top
NOREF#175  -  []  150.24 41.35 90 top
NOREF#176  -  []  137.76 0.45 90 top
NOREF#177  -  []  105.42 44.28 90 top
NOREF#178  -  []  134.78 5.93 90 top
NOREF#179  -  []  149.89 47.3 0 top
NOREF#180  -  []  135.03 49.95 0 top
NOREF#181  -  []  164.78 102.06 90 top
NOREF#182  -  []  8.6 4.49 90 top
NOREF#183  -  []  103.72 45.18 0 top
NOREF#184  -  []  46.67 59.69 0 top
NOREF#185  -  []  40 96.97 0 top
NOREF#186  -  []  50.15 116.68 0 top
NOREF#187  -  []  80.52 98.63 90 top
NOREF#188  -  []  36.02 96.79 90 top
NOREF#189  -  []  8.11 73.43 90 top
NOREF#190  -  []  36.52 98.54 90 top
NOREF#191  -  []  146.43 54.96 90 top
NOREF#192  -  []  115.37 100.6 90 top
NOREF#193  -  []  0 0 0 top
NOREF#194  -  []  143.14 87.11 0 top
NOREF#195  -  []  80.34 95.19 0 top
NOREF#196  -  []  27.24 58.42 90 top
NOREF#197  -  []  43.14 76.98 90 top
NOREF#198  -  []  67.69 45.54 0 top
NOREF#199  -  []  0.41 73.43 90 top
NOREF#200  -  []  -350.82 264.49 0 top
NOREF#201  -  []  59.33 30.77 0 top
NOREF#202  -  []  105.29 40.18 90 top
NOREF#203  -  [unnamed#2]  4.06 4.06 0 top
NOREF#204  -  []  3.81 76.03 90 top
NOREF#205  -  []  120.6 37.65 90 top
NOREF#206  -  []  143.14 107.59 0 top
NOREF#207  -  []  82.43 50.91 90 top
NOREF#208  -  []  164.78 102.06 90 top
NOREF#209  -  []  117.43 50.38 0 top
NOREF#210  -  []  119.75 43.38 0 top
NOREF#211  -  []  121.16 45.12 90 top
NOREF#212  -  []  121.57 44.63 0 top
NOREF#213  -  []  105.58 5.28 90 top
NOREF#214  -  []  10.33 88.23 0 top
NOREF#215  -  []  116.79 90.55 90 top
NOREF#216  -  []  80.52 100.13 90 top
NOREF#217  -  []  109.08 8.03 90 top
NOREF#218  -  []  89.47 61.02 0 top
NOREF#219  -  []  82.08 51.03 90 top
NOREF#220  -  []  127.08 30.24 0 top
NOREF#221  -  []  151.51 41.26 90 top
NOREF#222  -  []  118.16 116.78 90 top
NOREF#223  -  []  57.98 37.54 90 top
NOREF#224  -  []  81.73 50.91 0 top
NOREF#225  -  [unnamed#2]  147.83 60.33 0 top
NOREF#226  -  []  80.29 101.13 0 top
NOREF#227  -  []  123.13 54.49 90 top
NOREF#228  -  []  20.07 79.38 90 bottom
NOREF#229  -  [unnamed#2]  150.12 39 180 bottom
NOREF#230  -  []  38.46 27.69 180 bottom
NOREF#231  -  []  50.21 27.43 180 bottom
NOREF#232  -  []  128.65 8.64 180 bottom
NOREF#233  -  [unnamed#2]  6.6 10.29 180 bottom
NOREF#234  -  []  28.96 80.01 90 bottom
NOREF#235  -  [unnamed#2]  8.89 118.43 180 bottom
NOREF#236  -  []  17.91 105.03 270 bottom
NOREF#237  -  [unnamed#2]  139.34 120.04 180 bottom
P1  CMB-6544PF  [MIC_9MM_TH]  3.68 109.6 180 top
Q1  BSS138P  [SOT23_A]  134.92 72.44 0 top
Q3  PMDXB600UNEZ  [DFN1010N-6_0P35_1P15X1P05]  149.89 46.87 90 top
Q4  PMDXB600UNEZ  [DFN1010N-6_0P35_1P15X1P05]  149.89 41.79 90 top
Q8  PMV48XP  [SOT23_A]  125.76 117.94 0 top
Q15  2SK3018  [SOT323_3]  146.16 29.09 0 top
Q16  2SK3018  [SOT323_3]  146.16 23.34 0 top
R1  100  [RC0402_25]  127.03 120.93 0 top
R2  100  [RC0402_25]  121.79 120.21 270 top
R3  100k  [RC0402_25]  124.08 120.21 90 top
R4  47K  [RC0402_25]  27.69 116.59 0 top
R5  2.2K  [RC0402_25]  128.17 116.59 90 top
R6  2.2K  [RC0402_25]  130.45 116.59 270 top
R7  2.2K  [RC0402_25]  132.23 116.59 90 top
R8  2.2K  [RC0402_25]  143.43 114.33 180 top
R9  2.2K  [RC0402_25]  137.08 114.17 0 top
R10  100k  [RC0402_25]  56.24 113.84 0 top
R11  100k  [RC0402_25]  51.16 113.79 0 top
R12  2.2K  [RC0402_25]  121.41 111.25 180 top
R13  12.1K  [RC0402_25]  137.16 111.25 0 top
R14  0  [RC0402_25]  137.08 110.13 180 top
R15  2.2K  [RC0402_25]  121.41 109.98 180 top
R16  100k  [RC0402_25]  104.34 109.5 0 top
R17  2.2K  [RC0402_25]  121.46 108.64 180 top
R18  100  [RC0402_25]  104.34 108.48 180 top
R19  47K  [RC0402_25]  27.69 108.2 0 top
R20  2.2K  [RC0402_25]  104.34 107.47 180 top
R21  2.2K  [RC0402_25]  121.46 106.93 180 top
R22  470  [RC0402_25]  140.84 105.69 0 top
R23  2.2K  [RC0402_25]  115.82 104.9 180 top
R24  100k  [RC0402_25]  100.03 104.55 180 top
R25  2.2K  [RC0402_25]  112.78 103.63 180 top
R26  100  [RC0402_25]  100.03 103.4 180 top
R27  20  [RC0402_25]  34.29 103.12 0 top
R28  1.5K  [RC0402_25]  125.73 102.62 90 top
R29  2.2K  [RC0402_25]  126.87 102.62 90 top
R30  12.1K  [RC0402_25]  128.02 102.62 270 top
R31  12.1K  [RC0402_25]  129.16 102.62 270 top
R32  100k  [RC0402_25]  130.81 102.62 90 top
R33  12.1K  [RC0402_25]  131.95 102.62 90 top
R34  2.2K  [RC0402_25]  120.4 102.36 0 top
R35  100  [RC0402_25]  100.03 102.26 180 top
R36  2.2K  [RC0402_25]  112.78 102.11 0 top
R37  100k  [RC0402_25]  120.4 100.33 180 top
R38  20  [RC0402_25]  38.61 100.08 270 top
R39  100k  [RC0402_25]  96.34 97.1 90 top
R40  100  [RC0402_25]  76.56 97.23 270 top
R41  100k  [RC0402_25]  106.5 96.06 180 top
R42  2.2K  [RC0402_25]  32.61 95.15 0 top
R43  100k  [RC0402_25]  102.08 93.83 0 top
R44  100  [RC0402_25]  102.08 92.81 180 top
R45  33  [RC0402_25]  45.47 92.76 180 top
R46  100  [RC0402_25]  114.45 91.03 180 top
R47  2.2K  [RC0402_25]  102.08 91.8 180 top
R48  33  [RC0402_25]  45.47 91.36 180 top
R49  0  [R603-X2]  34.67 85.39 90 top
R50  100k  [RC0402_25]  120.87 84.07 90 top
R51  4.7K  [RC0402_25]  33.35 81.41 180 top
R52  100  [RC0402_25]  33.35 80.14 180 top
R53  47K  [RC0402_25]  136.65 79.48 180 top
R54  470  [RC0402_25]  146.86 79.1 0 top
R55  2.2K  [RC0402_25]  149.17 79.1 0 top
R56  1M  [RC0402_25]  97.21 75.92 180 top
R57  100  [RC0402_25]  33.35 76.07 180 top
R58  100  [RC0402_25]  71.24 75.92 90 top
R59  4.7K  [RC0402_25]  33.35 74.8 180 top
R60  100k  [RC0402_25]  137.85 72.92 270 top
R61  100k  [RC0402_25]  115.01 68.11 0 top
R62  4.7K  [RC0402_25]  33.35 70.23 180 top
R63  100  [RC0402_25]  33.35 68.96 180 top
R64  100  [RC0402_25]  33.35 64.9 180 top
R65  4.7K  [RC0402_25]  33.35 63.63 180 top
R66  4.7K  [RC0402_25]  65.54 47.82 270 bottom
R67  100k  [RC0402_25]  128.17 50.03 180 top
R68  100k  [RC0402_25]  128.17 49.04 0 top
R69  4.7K  [RC0402_25]  59.04 54.32 180 top
R70  100k  [RC0402_25]  128.17 48.1 180 top
R71  100k  [RC0402_25]  63.54 56.81 270 top
R72  0  [RC0402_25]  4.57 49.78 90 top
R73  0  [RC0402_25]  7.11 49.78 90 top
R74  0  [RC0402_25]  14.73 49.78 90 top
R75  0  [RC0402_25]  17.27 49.78 90 top
R76  0  [RC0402_25]  19.81 49.78 90 top
R77  0  [RC0402_25]  22.35 49.78 90 top
R79  0  [RC0402_25]  46.66 56.29 270 top
R80  0  [RC0402_25]  49.2 56.29 270 top
R81  100k  [RC0402_25]  128.17 47.11 0 top
R82  20K  [RC0603_OV]  128.17 53.23 180 top
R83  2.2K  [RC0402_25]  126.65 47.59 90 top
R84  2.2K  [RC0402_25]  125.7 47.59 90 top
R85  20K  [RC0603_OV]  128.17 51.55 180 top
R86  100k  [RC0402_25]  137.44 57.2 270 top
R87  100k  [RC0402_25]  142.52 57.2 270 top
R88  100k  [RC0402_25]  141.02 57.2 270 top
R89  0  [RC0402_25]  105.4 78.9 270 top
R90  100k  [RC0402_25]  101.6 35.83 90 top
R92  270  [RC0402_25]  147.47 49.9 0 top
R93  1K  [RC0402_25]  137.82 39.23 0 top
R94  1K  [RC0402_25]  140.36 39.23 0 top
R95  1K  [RC0402_25]  142.9 39.23 0 top
R96  422  [RC0402_25]  147.47 43.55 0 top
R97  270  [RC0402_25]  147.47 38.73 0 top
R98  2.2K  [RC0402_25]  147.47 34.41 0 top
R99  0  [RC0402_25]  36.58 11.43 90 top
R100  0  [RC0402_25]  38.86 11.43 90 top
R101  0  [RC0402_25]  41.66 11.43 90 top
R102  0  [RC0402_25]  44.2 11.43 90 top
R104  10K  [0402_CC]  72.59 86.52 90 bottom
R105  10K  [0402_CC]  71.25 86.52 270 bottom
R106  100  [RC0402_25]  8.64 41.99 0 bottom
R107  0  [RC0603_OV]  117.51 55.26 90 top
R108  100  [RC0402_25]  22.1 35.94 180 bottom
R109  100  [RC0402_25]  22.1 34.29 0 bottom
R110  100  [RC0402_25]  22.1 32.64 180 bottom
R111  100  [RC0402_25]  22.1 30.99 0 bottom
R112  100  [RC0402_25]  22.1 29.34 0 bottom
R113  100  [RC0402_25]  22.1 27.69 180 bottom
R114  100  [RC0402_25]  22.1 26.04 0 bottom
R115  100  [RC0402_25]  22.1 24.38 180 bottom
R116  2.2K  [RC0402_25]  87.34 102.68 180 top
R117  2.2K  [RC0402_25]  87.34 101.35 180 top
R118  1K  [RC0402_25]  95.9 83.24 180 top
R121  2.2K  [RC0402_25]  122.13 38.15 90 top
R123  100k  [RC0402_25]  100.58 35.83 270 top
R124  100k  [RC0402_25]  122.61 116.94 0 top
R125  0  [RC0402_25]  99.73 93.56 180 top
R126  2.2K  [RC0402_25]  130.05 99.68 0 top
R127  2.2K  [RC0402_25]  127 99.71 180 top
R128  100k  [RC0402_25]  140.15 3.9 180 top
R130  100  [RC0402_25]  62.07 110.65 0 top
R131  100k  [RC0402_25]  143.27 3.9 0 top
R132  0  [R603-X2]  145.61 9.02 90 top
R133  47K  [RC0402_25]  97.21 76.9 180 top
R134  100k  [RC0402_25]  142.15 34.11 270 top
R135  0  [RC0402_25]  81.64 104.58 90 top
R136  0  [RC0402_25]  76.56 103.05 90 top
R137  10K  [0402_CC]  79.07 104.43 270 top
R138  10K  [0402_CC]  76.56 99.27 270 top
R139  10K  [0402_CC]  82.82 104.44 270 top
R140  10K  [0402_CC]  76.57 101.2 90 top
R141  10K  [0402_CC]  82.67 95.45 0 top
R144  0  [R603-X2]  86.63 94.64 0 top
R145  0  [RC0402_25]  87.35 96.11 180 top
R146  100k  [RC0402_25]  113.84 86.39 270 top
R147  100k  [RC0402_25]  114.45 92.66 180 top
R148  100k  [RC0402_25]  105.79 85.72 180 bottom
R149  100k  [RC0402_25]  115.01 73.19 180 top
R200  22  [RC0402_25]  81.15 29.84 90 top
R201  0  [RC0402_25]  59.27 41.64 270 top
R202  0  [RC0402_25]  60.23 41.64 270 top
R203  0  [RC0402_25]  61.18 41.64 270 top
R204  0  [RC0402_25]  62.13 41.64 270 top
R205  0  [RC0402_25]  63.08 41.64 270 top
R206  0  [RC0402_25]  64.04 41.64 270 top
R207  0  [RC0402_25]  64.99 41.64 270 top
R208  0  [RC0402_25]  65.94 41.64 270 top
R209  10K  [0402_CC]  63.72 33.96 270 bottom
R210  0  [RC0402_25]  64.67 33.96 270 bottom
R211  0  [RC0402_25]  66.58 33.9 270 bottom
R212  0  [RC0402_25]  67.53 33.9 270 bottom
R213  0  [RC0402_25]  68.48 33.9 270 bottom
R215  0  [RC0402_25]  59.91 33.96 90 bottom
R216  0  [RC0402_25]  60.86 33.96 90 bottom
R217  0  [RC0402_25]  61.81 33.96 90 bottom
R218  0  [RC0402_25]  62.77 33.96 90 bottom
R221  0  [RC0402_25]  146.2 87.12 270 top
R222  0  [RC0402_25]  146.2 85.12 90 top
R224  510  [RC0402_25]  149.41 21.34 270 top
R225  510  [RC0402_25]  149.41 26.84 270 top
R226  4.7K  [RC0402_25]  72.83 30.09 90 bottom
R227  4.7K  [RC0402_25]  71.75 30.09 90 bottom
R228  4.7K  [RC0402_25]  146.16 20.84 0 top
R229  4.7K  [RC0402_25]  146.02 26.84 0 top
R231  10K  [0402_CC]  63.72 35.55 90 bottom
R240  51K  [RC0402_25]  83.53 47.82 270 top
R241  51K  [RC0402_25]  77.04 54.32 180 top
R242  0  [RC0402_25]  77.04 53.32 180 top
R243  0  [RC0402_25]  88.14 53.32 0 top
R244  0  [RC0402_25]  83.53 56.81 90 top
R245  0  [RC0402_25]  88.14 54.32 180 top
R246  0  [RC0402_25]  82.53 56.81 270 top
R247  0  [RC0402_25]  82.53 47.82 90 top
R248  0  [RC0402_25]  80.53 56.81 270 top
R249  10K  [0402_CC]  77.04 51.32 0 top
R250  10K  [0402_CC]  79.53 56.81 270 top
R251  0  [RC0402_25]  81.53 47.82 90 top
R300  0  [R603-X2]  112.96 33.01 90 top
R301  0  [R603-X2]  114.81 33.01 90 top
R302  0  [R603-X2]  119.58 33.01 90 top
R303  0  [R603-X2]  127.08 33.01 90 top
R304  0  [R603-X2]  129.58 33.01 90 top
R305  0  [R603-X2]  132.08 33.01 90 top
R306  0  [R603-X2]  121.43 34.6 270 top
R307  0  [R603-X2]  123.21 34.6 270 top
R308  100k  [RC0402_25]  123.21 37.2 270 top
R309  4.7K  [RC0402_25]  125.6 34.6 270 top
R310  100k  [RC0402_25]  124.51 34.6 270 top
R350  0  [RC0402_25]  65.04 47.82 90 top
R351  0  [RC0402_25]  59.04 53.32 0 top
R352  0  [RC0402_25]  61.54 47.82 90 top
R353  0  [RC0402_25]  70.04 51.32 180 top
R354  0  [RC0402_25]  70.04 53.32 180 top
R355  0  [RC0402_25]  66.04 47.82 90 top
R356  0  [RC0402_25]  64.54 56.81 270 top
R357  0  [RC0402_25]  66.54 56.81 270 top
R358  0  [RC0402_25]  65.54 56.81 270 top
R359  0  [RC0402_25]  70.04 52.32 180 top
R360  0  [RC0402_25]  70.04 50.32 180 top
R361  0  [RC0402_25]  70.04 49.32 180 top
R362  10K  [0402_CC]  62.54 56.69 270 top
R363  10K  [0402_CC]  59.04 51.32 0 top
R364  0  [RC0402_25]  63.54 47.82 270 top
R365  0  [RC0402_25]  62.54 47.82 270 top
R372  100k  [RC0402_25]  145.56 13.14 90 top
R373  0  [RC0402_25]  147.52 17.07 180 top
R377  0  [R603-X2]  8.61 2.04 0 top
R378  0  [R603-X2]  104 3.99 180 top
R379  0  [R603-X2]  87.69 44.09 270 top
R380  0  [R603-X2]  94.8 44.09 270 top
R383  100k  [RC0402_25]  100.73 82.19 0 top
R384  0  [R603-X2]  93.02 44.09 270 top
R385  0  [R603-X2]  71.18 58.32 90 top
R386  0  [R603-X2]  72.95 58.32 90 top
R387  0  [R603-X2]  76.51 58.32 90 top
R388  0  [R603-X2]  74.73 58.32 90 top
R389  0  [R603-X2]  91.24 44.09 270 top
R390  0  [R603-X2]  89.46 44.09 270 top
R391  0  [R603-X2]  85.91 44.09 270 top
R392  0  [R603-X2]  98.35 44.09 270 top
R393  0  [R603-X2]  96.58 42.57 90 top
R394  0  [R603-X2]  58.44 59.66 180 top
R395  0  [R603-X2]  58.44 61.46 180 top
R396  0  [R603-X2]  84.13 44.09 270 top
R397  0  [R603-X2]  58.44 63.24 180 top
R398  0  [R603-X2]  58.44 65.02 180 top
R399  0  [RC0402_25]  43.58 88.63 180 top
R400  0  [RC0402_25]  43.59 87.68 180 top
R401  0  [RC0402_25]  45.47 90.35 0 top
R402  0  [RC0402_25]  43.58 90.35 180 top
R403  0  [RC0402_25]  49.29 97.45 90 top
R404  0  [RC0402_25]  43.58 89.52 180 top
R405  0  [RC0402_25]  95.9 82.19 180 top
R406  0  [RC0402_25]  50.56 100.6 270 top
R407  2.2K  [RC0402_25]  76.2 114.63 90 top
R408  2.2K  [RC0402_25]  41.55 57.27 90 top
R409  2.2K  [RC0402_25]  52.09 101.35 0 top
R410  2.2K  [RC0402_25]  58.56 101.35 180 top
R411  2.2K  [RC0402_25]  52.09 99.85 0 top
R412  2.2K  [RC0402_25]  58.56 99.85 180 top
R413  2.2K  [RC0402_25]  100.73 83.24 0 top
R414  2.2K  [RC0402_25]  98.44 83.24 180 top
R415  2.2K  [RC0402_25]  73.24 33.96 270 bottom
R416  2.2K  [RC0402_25]  74.2 33.96 270 bottom
R417  0  [RC0402_25]  88.14 51.32 0 top
R418  0  [RC0402_25]  81.53 56.81 90 top
R419  0  [RC0402_25]  84.53 56.81 90 top
R420  0  [RC0402_25]  88.14 52.32 0 top
R421  0  [RC0402_25]  88.14 50.32 0 top
R422  0  [RC0402_25]  88.14 49.32 0 top
R423  0  [RC0402_25]  81.15 32.13 270 top
RT1  100K  [RC0402_25]  123.1 52.27 270 bottom
SH2  0  [SH0402]  87.34 103.84 0 top
SH3  0  [SH0402]  87.35 100.2 0 top
SH4  0  [SH0603]  110.02 76.93 270 top
SH11  0  [SH0603]  74.04 112.01 180 top
SH12  0  [SH0603]  74.04 110.65 180 top
SH13  0  [SH0603]  74.04 109.35 180 top
SH14  0  [SH0603]  74.04 107.95 180 top
SH17  0  [SH0603]  61.84 112.55 180 top
SH18  0  [SH0603]  61.85 107.57 180 top
SH19  0  [SH0603]  61.85 106.2 180 top
SH20  0  [SH0603]  61.85 104.78 180 top
SH21  0  [SH0603]  61.85 102.39 180 top
SW1  KMR221NG LFS  [SW4_4P2X2P8_SM]  55.82 118.82 270 top
SW2  KMR221NG LFS  [SW4_4P2X2P8_SM]  50.95 118.73 270 top
SW3  KMR221NG LFS  [SW4_4P2X2P8_SM]  118.96 118.83 270 top
SW4  SKRPABE010  [SW4_SKRP]  110.11 41.07 180 top
SW5  90HBW03PT  [SW_DIP6_2P54_7P37X9P65MM_SM]  139.86 46.26 90 top
TP1  -  [TPAD_050]  133.78 116.28 0 top
TP2  -  [TPAD_050]  136.32 116.28 0 top
TP3  -  [TPAD_050]  138.86 116.28 90 top
TP4  -  [TPAD_050]  141.4 116.28 0 top
TP5  -  [TPAD_050]  143.94 116.28 0 top
TP6  -  [TPAD_050]  48.64 93.95 0 top
TP7  -  [TPAD_050]  48.64 91.87 0 top
TP8  -  [TPAD_050]  80.57 92.86 0 top
TP9  -  [TPAD_050]  48.23 87.68 0 top
TP10  -  [TPAD_050]  46.19 87.68 0 top
TP11  TEST POINT WHITE  [TEST_LOOP]  51.82 79.52 0 top
TP12  -  [TPAD_050]  77.65 76.42 0 top
TP13  -  [TPAD_050]  141.88 76.83 0 top
TP14  -  [TPAD_050]  105.3 51.89 0 top
TP15  TEST POINT WHITE  [TEST_LOOP]  123.13 61.11 0 top
TP16  -  [TPAD_050]  107.35 51.89 0 top
TP17  TEST POINT WHITE  [TEST_LOOP]  127.67 55.32 180 top
TP18  -  [TPAD_050]  113.41 54.61 0 top
TP19  TEST POINT WHITE  [TEST_LOOP]  115.11 47.45 0 top
TP20  TEST POINT WHITE  [TEST_LOOP]  132.72 45.85 0 top
TP21  -  [TPAD_050]  99.6 54.32 0 top
TP22  -  [TPAD_050]  101.12 51.89 180 top
TP23  -  [TPAD_050]  103.78 54.32 0 top
TP24  -  [TPAD_050]  99.1 51.87 0 top
TP25  -  [TPAD_050]  101.74 54.32 180 top
TP26  -  [TPAD_050]  103.26 51.89 180 top
TP27  -  [TPAD_050]  115.59 54.59 270 top
TP28  -  [TPAD_050]  122.46 50.62 180 bottom
TP29  -  [TPAD_050]  125.16 58.37 0 top
TP30  -  [TPAD_050]  105.7 68.02 0 top
TP31  -  [TPAD_050]  107.73 68.02 0 top
TP32  -  [TPAD_050]  141.73 5.52 270 top
TP33  -  [TPAD_050]  143.78 5.49 270 top
TP34  -  [TPAD_050]  139.65 5.52 270 top
TP37  -  [TPAD_050]  77.41 104.95 180 top
TP38  -  [TPAD_050]  146.98 91.47 0 top
TP39  -  [TPAD_050]  115.33 116.94 0 top
TP40  -  [TPAD_050]  145.56 17.07 0 top
TP41  -  [TPAD_050]  150 14.93 0 top
TP42  -  [TPAD_050]  92.19 94.64 0 top
TP43  -  [TPAD_050]  81.53 45.32 90 top
TP44  -  [TPAD_050]  72.14 51.32 270 top
TP45  -  [TPAD_050]  62.54 45.82 180 top
TP46  -  [TPAD_050]  96.58 47.02 0 top
U1  LPC4322JET100  [FBGA100_0P8_9X9]  129.62 109.73 180 top
U2  74LVC1T45GW,125  [SOT-363_0P65_SMT]  107.62 106.71 180 top
U3  74AVC2T45DP  [MSOP_8P_0P65_3X3MM]  105.28 101.9 90 top
U4  74AVC4TD245BQ  [DHVQFN16_0P5_3P6X2P6]  116.59 101.85 180 top
U5  74LVC1T45GW,125  [SOT-363_0P65_SMT]  103.43 96.7 0 top
U6  FXOS8700CQ  [QFN5X3_0P5_3X3]  81.79 99.63 180 top
U7  NX3DV2567GU  [PQFN16_0P4_2P65X1P85]  98.58 96.11 270 top
U8  WM8904  [QFN32_0P4_4P1SQ_2P8EP]  41.4 95 180 top
U9  74AVC4TD245BQ  [DHVQFN16_0P5_3P6X2P6]  118.01 91.8 180 top
U10  74LVC1T45GW,125  [SOT-363_0P65_SMT]  105.66 91.41 180 top
U12  TFA9894DUK  [WLCSP48_0P4_2P51X3P55]  44.7 77.98 270 top
U13  NX5P3090UK  [WLCSP12_0P4_1P38X1P68MM_SMDP]  136.86 77.55 90 top
U14  NCP1117ST25T3G  [SOT223]  124.99 75.18 270 top
U15  NC7SZ32P5X  [SC70-5]  51.82 75.18 180 top
U16  74LVC1G04GW  [SC70-5]  51.82 70.1 180 top
U17  TFA9894DUK  [WLCSP48_0P4_2P51X3P55]  44.7 67.06 270 top
U18  MIMXRT685  [BGA176_0P5_9X9]  93.47 65.02 0 top
U19  MX25UM51345GXDI00  [PBGA24_1_6X8MM]  64.54 52.32 90 top
U20  PCA9420BSZ  [HVQFN24_0P4_3P1X3P1_EP]  123.06 51.05 90 top
U21  PRTR5V0U2X  [SOT143B]  144.09 108.59 180 top
U22  PRTR5V0U2X  [SOT143B]  144.09 86.11 180 top
U23  NCP692MN33T2G  [DFN6_0P95_3X3]  104.24 36.27 0 top
U24  74LVC07APW  [TSSOP14]  141.83 12.55 270 top
U25  NCP692MN33T2G  [DFN6_0P95_3X3]  104.72 49.11 180 top
U26  74AVC2T45  [SSOP8_DCU]  118 96.46 90 top
U27  74LVC1T45GW,125  [SOT-363_0P65_SMT]  118.19 83.01 0 top
U28  74LVC1T45GW,125  [SOT-363_0P65_SMT]  118.19 85.88 0 top
U30  74LVC1G04GW  [SC70-5]  51.66 83.38 0 top
U32  74LVC2G07  [SOT363]  147.52 14.28 90 top
U34  NTB0104BQ  [DHVQFN14_3X2P5MM]  45.69 83.1 180 top
U35  NTB0102DP  [TSSOP8_A]  55.23 97.52 180 top
U36  NTS0102GD  [XSON8_0P5_3P1X2P1]  55.13 100.6 0 top
U40  SPH0641LM4H-1  [MIC5_3P6X2P75MM]  9.14 5.32 90 top
U41  SPH0641LM4H-1  [MIC5_3P6X2P75MM]  103.78 6.66 90 top
U108  APS6408L-OBM-BA  [PBGA24_1_6X8MM]  82.53 52.32 90 top
Y1  12MHZ  [XTL2_11P6X4P85_SM]  140.26 99.49 180 top
Y2  24MHZ  [XTLOSC4_3P2X2P5MM_SM]  97.34 73.81 180 top
Y3  32.768KHZ  [XTAL2-3P2X1P5-SM]  103.38 69.27 270 top
Y8  32.768KHZ  [XTAL4_3P3X2P6_SM_FL]  81.92 26.8 90 top

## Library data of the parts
BH1 = MOUNT_HOLE
C1 C8 C13 C16 C21-C24 C33 C36 C37 C42 C47 C48 C53 C59 C63 C67 C72 C74 C76-C78 C80 C82-C84 C90 C93-C95 C98 C118 C129 C131 C132 C136 C138-C140 C143 C218 C322 C328-C333 C336 C337 = CAP_NP: signal model: DEFAULT_CAPACITOR_100000pF_2_1
C2 C19 C27 C29 C52 C71 C89 C91 C92 C217 C316 C317 = CAP_NP: signal model: DEFAULT_CAPACITOR_1e+06pF_2_1
C3 C39 C40 C46 C55 = CAP_NP: signal model: DEFAULT_CAPACITOR_220000pF_2_1
C4-C6 C11 C15 C25 C26 C41 C60 C62 C75 C88 C96 C97 C219 = CAP_NP: signal model: DEFAULT_CAPACITOR_4.7e+06pF_2_1
C7 C9 C17 C18 C28 C32 C35 C58 C79 C81 C86 C100 = CAP_NP: signal model: DEFAULT_CAPACITOR_10000pF_2_1
C10 C14 C99 = CAP_NP: signal model: DEFAULT_CAPACITOR_2.2e+07pF_2_1
C12 C50 = CAP_NP: signal model: DEFAULT_CAPACITOR_10.000000pF_2_1
C20 C133 = CAP_NP: signal model: DEFAULT_CAPACITOR_1e+08pF_2_1
C30 = CAP_NP: signal model: DEFAULT_CAPACITOR_1.200000pF_2_1
C31 C43 C44 C49 C61 C64 C69 C70 C127 C128 C135 C137 C250 C252 = CAP_NP: signal model: DEFAULT_CAPACITOR_1e+07pF_2_1
C34 C57 = CAP_NP: signal model: DEFAULT_CAPACITOR_2.2e+06pF_2_1
C38 = CAP_NP: signal model: DEFAULT_CAPACITOR_56.000000pF_2_1
C45 C54 C65 C73 = CAP_NP: signal model: DEFAULT_CAPACITOR_18.000000pF_2_1
C51 C56 = CAP_NP: signal model: DEFAULT_CAPACITOR_27.000000pF_2_1
C66 C87 = CAP_NP: signal model: DEFAULT_CAPACITOR_1000pF_2_1
C68 = CAP_NP: Tolerance: TOLERANCE; User Part Number: 150-80124; signal model: DEFAULT_CAPACITOR_220000pF_2_1
C85 C130 = CAP_NP: signal model: DEFAULT_CAPACITOR_2.2e+08pF_2_1
C101 = CAP_NP: signal model: DEFAULT_CAPACITOR_3.3e+06pF_2_1
C102 C104 C106 C112 C114 C120 C122 C123 C125 C251 C253 C319 C320 C338 = CAP_NP: Tolerance: TOLERANCE; User Part Number: 150-80124; signal model: DEFAULT_CAPACITOR_100000pF_2_1
C103 C108 C113 C117 C119 = CAP_NP: Tolerance: TOLERANCE; User Part Number: 150-80124; signal model: DEFAULT_CAPACITOR_2.2e+07pF_2_1
C105 C116 = CAP_NP: Tolerance: TOLERANCE; User Part Number: 150-80124; signal model: DEFAULT_CAPACITOR_2200pF_2_1
C107 C109 C126 = CAP_NP: Tolerance: TOLERANCE; User Part Number: 150-80124; signal model: DEFAULT_CAPACITOR_4.7e+06pF_2_1
C110 = CAP_NP: Tolerance: TOLERANCE; User Part Number: 150-80124; signal model: DEFAULT_CAPACITOR_1e+06pF_2_1
C111 = CAP_NP: Tolerance: TOLERANCE; User Part Number: 150-80124; signal model: DEFAULT_CAPACITOR_3.3e+07pF_2_1
C115 = CAP_NP: Tolerance: TOLERANCE; User Part Number: 150-80313; signal model: DEFAULT_CAPACITOR_100000pF_2_1
C121 = CAP_NP: Tolerance: TOLERANCE; User Part Number: 150-80124; signal model: DEFAULT_CAPACITOR_18.000000pF_2_1
C124 = CAP_NP: Tolerance: TOLERANCE; User Part Number: 150-80124; signal model: DEFAULT_CAPACITOR_1e+07pF_2_1
C134 = CAP_NP: signal model: DEFAULT_CAPACITOR_220.000000pF_2_1
C321 = CAP_NP: Tolerance: TOLERANCE; User Part Number: 150-80313; signal model: DEFAULT_CAPACITOR_10000pF_2_1
D1 D2 D8-D11 D15 D22 D23 = LED
D3 D4 D14 = DIODE_TVS_C1C2A3
D5 D12 = DIODE_SCHTKY
D6 D7 = DIODE_SCH_123
D13 = DIODE_ARRAY_5CH
D26 = DIODE_TVS
FB1 = BEAD: tolerance: 25%; signal model: DEFAULT_RESISTOR_330.000000OHM_2_1
J1 J2 = CONN_HDR_5X2
J3 J4 = SJ-3524-SMT_4P
J5 J6 = USB_MINI_B_SKT
J7 = MICRO_USB_CONN_9PIN
J11 J20 = TB2
J16 JP2 JP6-JP8 JP11-JP13 JP16 JP21 JP22 = CONN_HDR_3X1
J18 = HDR-1X4
J19 = CONN_HDR_10X2
J21 J25 J26 JP1 JP3 JP4 JP9 JP10 JP14 JP15 JP17-JP20 JP23-JP30 JS1-JS3 JS5-JS17 = CONN_HDR_2X1
J24 = CONN_3P_POWERJACK
J27 J29 = CONN_HDR_8X1
J28 = RCPT 1X10
J30 = CONN_HDR_6X1
J31 = HDR-2X7
J32 = CONN_SDCARD_PUSH_PULL_9P_SH2
J35 = CONN_HDR_2X2
J36 = CONN_HDR_6X2
J38 = MICTOR38P
J45 = CON_67_FEMALE_RA
J47 = CONN_HDR_9X1
L1 L8 = BEAD: signal model: DEFAULT_RESISTOR_330.000000OHM_2_1
L2 L4 L13 = INDUCTOR: signal model: DEFAULT_RESISTOR_120.000000OHM_2_1
L3 = INDUCTOR: signal model: DEFAULT_INDUCTOR_2200nH_2_1
L5 L6 L9 L10 = INDUCTOR_FERRITE: signal model: DEFAULT_RESISTOR_120.000000OHM_2_1
L7 = INDUCTOR: signal model: DEFAULT_RESISTOR_330.000000OHM_2_1
L11 L12 = INDUCTOR: tolerance: 20%; signal model: DEFAULT_RESISTOR_120.000000OHM_2_1
P1 = MIC
Q1 = MOSFET_N
Q3 Q4 = NMOS_DUAL_PMDXB600UNE_8P
Q8 = MOSFET_P
Q15 Q16 = 2SK3018
R1 R10 R11 R13 R23 R24 R30 R35 R43 R72-R77 R80 R83 R86 R90 R99-R102 R104 R105 R110 R113 R115 R137-R141 R209 R231 = RES: signal model: DEFAULT_RESISTOR_10000OHM_2_1
R2 R3 R60 R66 R69 R71 R79 R88 R93 R95 R96 R118 = RES: signal model: DEFAULT_RESISTOR_1000.000000OHM_2_1
R4 R6 R25 R33 R45 R47 R53-R55 R116 R117 R121 R126 R127 R407-R416 = RES: signal model: DEFAULT_RESISTOR_2200OHM_2_1
R5 R9 R12 R15 R17 R21 R22 R28 R31 R32 R38 R41 R42 R51 R61 R68 R81 R82 R98 R111 R123 R124 R128 R131 R134 R146-R149 R308 R310 R372 R383 = RES: signal model: DEFAULT_RESISTOR_100000OHM_2_1
R7 R14 R16 R18 R26 R37 R46 R56 R84 R89 R92 R94 R106 R125 R135 R136 R145 R201-R208 R210-R213 R215-R218 R221 R222 R242 R247 R251 R351 R352 R355 R359 R364 R373 R399-R406 R423 = RES: signal model: DEFAULT_RESISTOR_0.001OHM_2_1
R8 R20 = RES: signal model: DEFAULT_RESISTOR_62.000000OHM_2_1
R19 R29 R44 R59 R65 R107 = RES: signal model: DEFAULT_RESISTOR_33.000000OHM_2_1
R27 R48 R70 = RES: signal model: DEFAULT_RESISTOR_12000OHM_2_1
R34 R36 R40 R50 R87 R108 R109 R114 R226-R229 R309 = RES: signal model: DEFAULT_RESISTOR_4700OHM_2_1
R39 = RES: signal model: DEFAULT_RESISTOR_200000OHM_2_1
R49 = RES_0603_X2: Tolerance: X; User Part Number: 470-80866; signal model: DEFAULT_RESISTOR_100000OHM_2_1
R52 R57 R58 R63 R64 R130 = RES: signal model: DEFAULT_RESISTOR_100.000000OHM_2_1
R62 R133 = RES: signal model: DEFAULT_RESISTOR_47000OHM_2_1
R67 = RES: signal model: DEFAULT_RESISTOR_560.000000OHM_2_1
R85 = RES: signal model: DEFAULT_RESISTOR_11000OHM_2_1
R97 = RES: signal model: DEFAULT_RESISTOR_15000OHM_2_1
R112 = RES: signal model: DEFAULT_RESISTOR_180000OHM_2_1
R132 R144 = RES_0603_X2: Tolerance: X; User Part Number: 470-80866
R200 = RES: signal model: DEFAULT_RESISTOR_22.000000OHM_2_1
R224 R225 = RES: signal model: DEFAULT_RESISTOR_510.000000OHM_2_1
